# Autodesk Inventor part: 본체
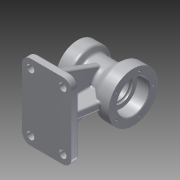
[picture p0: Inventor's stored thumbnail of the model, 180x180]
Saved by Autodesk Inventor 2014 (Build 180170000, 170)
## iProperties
Created: 2015-08
Part Number: 본체
Material: 알루미늄 6061
Document SubType Name: Modeling
Designer: Owner
Density: 2.71 g/cm^3
Appearance: 알루미늄 - 평지
Author: Owner
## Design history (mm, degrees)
sketch "스케치1"
  geometry: C1 r 40 at (0, 0); 1 further point
  constraints: 1 centre point, 1 coincident
  dimensions: "d0" = 80 diameter of C1
extrude "돌출1" new body sketch "스케치1" distance "d1" = 20; taper "d2" = 0 deg
node "작업 평면1"
sketch "스케치2"
  geometry: C1 r 35 at (0, 0); 1 further point
  constraints: 1 centre point, 1 coincident
  dimensions: "d4" = 70 diameter of C1
extrude "돌출2" join sketch "스케치2" distance "d5" = 20; taper "d6" = 0 deg
sketch "스케치3"
  geometry: L1 (0, 40)-(20, 40) reference; L2 (20, 40)-(20, -40) reference; L3 (20, -40)-(0, -40) reference; L4 (0, -40)-(0, 40) reference; L5 (-70, 35)-(-50, 35) reference; L6 (-50, 35)-(-50, -35) reference; L7 (-50, -35)-(-70, -35) reference; L8 (-70, -35)-(-70, 35) reference; L9 (0, 0)-(-50, 0); L10 (0, 40)-(-16.685, 26); L11 (0, 40)-(28.445, 40); L12 (-16.685, 26)-(-44.804, 26); L13 (-50, 35)-(-44.804, 26); L14 (-50, 35)-(-23.111, 35); L15 (-50, 35)-(-50, 0); L16 (0, 40)-(0, 0)
  constraints: 16 end point, 2 horizontal, 1 collinear, 1 midpoint, 1 perpendicular
  dimensions: "d7" = 140 deg angle of L10 L11; "d9" = 60 deg angle of L13 L14
revolve "회전1" sketch "스케치3" stored, may be unused: angle "d10" = 90 deg
node "작업 평면2"
sketch "스케치4"
  geometry: L1 (50, 35)-(50, -35) reference; L2 (70, -35)-(70, 35) reference; L3 (70, 0)-(60, 0); L4 (70, 0)-(70, -61); L5 (70, 0)-(70, 61); L6 (70, -61)-(-10, -61); L7 (70, 61)-(-10, 61); L8 (-10, 61)-(-10, -61); 1 further point
  constraints: 12 end point, 2 equal length, 2 perpendicular, 1 midpoint
  dimensions: "d12" = 10 distance of L3.start L3.end; "d19" = 80 distance of L4.end L6.end
extrude "돌출3" join sketch "스케치4" distance "d17" = 12; taper "d18" = 0 deg
sketch "스케치5"
  geometry: L1 (-44.804, -26)-(-50, -35) reference; L2 (-50, -35)-(-70, -35) reference; L3 (-70, -35)-(-70, 35) reference; L4 (-70, 35)-(-50, 35) reference; L5 (-50, 35)-(-44.804, 26) reference; L6 (-44.804, 26)-(-16.685, 26) reference; L7 (-16.685, 26)-(0, 40) reference; L8 (0, 40)-(20, 40) reference; L9 (20, 40)-(20, -40) reference; L10 (20, -40)-(0, -40) reference; L11 (0, -40)-(-16.685, -26) reference; L12 (-16.685, -26)-(-44.804, -26) reference; L13 (-70, -90)-(-70, -78) reference; L14 (-70, -78)-(10, -78) reference; L15 (10, -78)-(10, -90) reference; L16 (10, -90)-(-70, -90) reference; L17 (-70, -78)-(-60, -78); L18 (-60, -78)-(-60, -30.5); L19 (10, -78)-(0, -78); L20 (0, -78)-(9.169, -26); L21 (9.169, -26)-(-13.066, -13.163); L22 (-13.066, -13.163)-(-38.547, -15.162); L23 (-38.547, -15.162)-(-60, -30.5); 1 further point
  constraints: 14 end point, 2 perpendicular, 2 point on line
  dimensions: "d20" = 10 distance of L13.end L17.end; "d21" = 10 distance of L14.end L19.end; "d22" = 80 deg angle of L19 L20
extrude "돌출4" join sketch "스케치5" stored distance "d23" = 12; taper "d24" = 0 deg
node "작업 평면3"
sketch "스케치6"
  geometry: L1 (0, 0)-(0, 12) reference; L2 (0, 12)-(55, 12) reference; L3 (55, 12)-(55, 64.702) reference; L4 (67, 64.702)-(67, 12) reference; L5 (67, 12)-(122, 12) reference; L6 (122, 12)-(122, 0) reference; L7 (122, 0)-(0, 0) reference; L8 (0, 12)-(10, 12); L9 (10, 12)-(34.734, 79.956); L10 (10, 12)-(82.318, 12); L11 (61, 61.769)-(61, 12); L12 (61, 12)-(10, 12); L13 (61, 61.769)-(61, 90); L14 (61, 90)-(40.606, 82.563); L15 (34.734, 79.956)-(39.044, 91.799); L16 (39.044, 91.799)-(40.606, 82.563); A1 r 26 centre (61, 90) between (67, 64.702) and (55, 64.702) reference; 1 further point
  constraints: 18 end point, 2 collinear, 2 perpendicular, 1 equal length, 1 horizontal, 1 point on line
  dimensions: "d25" = 10 distance of L1.end L8.end; "d26" = 70 deg angle of L10 L9
extrude "돌출5" join sketch "스케치6" stored distance "d27" = 12; taper "d28" = 0 deg
sketch "스케치7"
  geometry: C1 r 40 at (0, 0) reference; C2 r 26 at (0, 0)
  constraints: 1 centre point, 1 coincident
  dimensions: "d29" = 52 diameter of C2
extrude "돌출6" cut sketch "스케치7" distance "d30" = 17; taper "d31" = 0 deg
sketch "스케치8"
  geometry: C1 r 35 at (0, 0) reference; C2 r 20 at (0, 0)
  constraints: 1 centre point, 1 coincident
  dimensions: "d32" = 40 diameter of C2
extrude "돌출7" cut sketch "스케치8" distance "d33" = 20; taper "d34" = 0 deg
sketch "스케치9"
  geometry: C1 r 20 at (0, 0) reference; C2 r 16 at (0, 0)
  constraints: 1 centre point, 1 coincident
  dimensions: "d82" = 32 diameter of C2
node "작업 평면4"
sketch "스케치12" dims "d55" = 54
  geometry: C1 r 35 at (0, 0) reference; C2 r 2 at (0, 27); 1 further point
  constraints: 1 centre point, 1 coincident, 1 vertical alignment, 2 other
  dimensions: "d56" = 4 diameter of C2
hole "구멍2" sketch "스케치12" at (0, 27) diameter "d57" = 3.242; stored, may be unused: countersink angle "d61" = 90 deg, drill point angle "d63" = 118 deg; dims "d58" = 10, "d59" = 4, "d60" = 2, "d62" = 13
sketch "스케치14" dims "d67" = 66
  geometry: C1 r 40 at (0, 0) reference; C2 r 2 at (0, 33); 1 further point
  constraints: 1 centre point, 1 coincident, 1 vertical alignment, 2 other
  dimensions: "d68" = 4 diameter of C2
hole "구멍3" sketch "스케치14" at (0, 33) diameter "d69" = 3.242; stored, may be unused: countersink angle "d73" = 90 deg, drill point angle "d75" = 118 deg; dims "d70" = 10, "d71" = 4, "d72" = 2, "d74" = 13
sketch "스케치15"
  geometry: C1 r 26 at (0, 0) reference; C2 r 26 at (0, 0)
  constraints: 1 centre point, 1 coincident, 1 concentric
extrude "돌출11" cut sketch "스케치9" distance "d83" = 70; taper "d84" = 0 deg
sketch "스케치16"
  geometry: L1 (86.091, 83.185)-(112, 12) reference; L2 (67, 12)-(112, 12) reference; L3 (67, 64.702)-(67, 12) reference; L4 (55, 12)-(55, 64.702) reference; L5 (10, 12)-(55, 12) reference; L6 (10, 12)-(35.909, 83.185) reference; L7 (112, 12)-(122, 12) reference; L8 (122, 12)-(122, 0) reference; L9 (122, 0)-(0, 0) reference; L10 (0, 0)-(0, 12) reference; L11 (0, 12)-(10, 12) reference; L12 (55, 12)-(61, 12); L13 (61, 12)-(61, 30); L14 (37, 42)-(37, 36); L15 (31, 36)-(31, 30); L16 (43, 36)-(43, 30); L17 (85, 30)-(85, 24); L18 (79, 36)-(79, 30); L19 (91, 36)-(91, 30); C1 r 16 at (61, 90) reference; A1 r 26 centre (61, 90) between (35.909, 83.185) and (55, 64.702) reference; A2 r 26 centre (61, 90) between (86.091, 83.185) and (35.909, 83.185) reference; A3 r 26 centre (61, 90) between (67, 64.702) and (86.091, 83.185) reference; A4 r 6 centre (37, 30) between (31, 30) and (43, 30); A5 r 6 centre (37, 36) between (43, 36) and (31, 36); A6 r 6 centre (85, 30) between (79, 30) and (91, 30); A7 r 6 centre (85, 36) between (91, 36) and (79, 36)
  constraints: 16 end point, 11 point on circle, 5 tangent, 4 centre point, 4 parallel, 1 collinear, 1 perpendicular
  dimensions: "d85" = 18 distance of L12.end L13.end; "d87" = 24 distance of L13.end L17.start
extrude "돌출12" cut sketch "스케치16" distance "d91" = 70; taper "d92" = 0 deg
fillet "모깎기1" dims "d93" = 14
sketch "스케치17"
  geometry: A1 r 14 centre (-56, -47) between (-70, -47) and (-56, -61) reference; A2 r 14 centre (-4, -47) between (-4, -61) and (10, -47) reference; A3 r 14 centre (-4, 47) between (10, 47) and (-4, 61) reference; A4 r 14 centre (-56, 47) between (-56, 61) and (-70, 47) reference; 1 further point
hole "구멍4" sketch "스케치17" at (-56, -47), (-4, -47), (-4, 47), (-56, 47) diameter "d94" = 12; stored, may be unused: countersink angle "d98" = 90 deg, drill point angle "d100" = 0 deg; dims "d95" = 10, "d96" = 4, "d97" = 2, "d99" = 30
sketch "스케치18"
  geometry: L1 (-36, -78)-(-60, -78) reference; L2 (-60, -78)-(-44, -78); L3 (-44, -78)-(-44, -54); 2 further points
  constraints: 4 end point, 1 coincident, 1 perpendicular, 1 point on line, 1 other
  dimensions: "d101" = 16 distance of L1.end L2.end; "d102" = 24 distance of L2.end L3.end
feature "엠보싱1" sketch "스케치18" dims "d103" = 0.5, "d104" = 0
fillet "모깎기2" dims "d105" = 5
chamfer "모따기1" distance "d106" = 1; stored, may be unused: second distance "d107" = 2, angle "d108" = 45 deg
fillet "모깎기5" dims "d111" = 3
fillet "모깎기6" dims "d112" = 3
fillet "모깎기7" dims "d113" = 3
fillet "모깎기8" dims "d114" = 3
fillet "모깎기9" dims "d115" = 3
fillet "모깎기10" dims "d116" = 3
fillet "모깎기11" dims "d117" = 3
extrude "돌출13" cut sketch "스케치15" distance "d118" = 3; taper "d119" = 0 deg
sketch "스케치19"
  geometry: C1 r 16 at (0, 0) reference; C2 r 26 at (0, 0) reference; C3 r 19 at (0, 0)
  constraints: 1 centre point, 1 coincident
  dimensions: "d120" = 38 diameter of C3
extrude "돌출14" cut sketch "스케치19" distance "d121" = 3; taper "d122" = 0 deg
fillet "모깎기12" dims "d123" = 3
sketch "스케치20"
  geometry: C1 r 16 at (0, 0) reference; C2 r 20 at (0, 0) reference; C3 r 20 at (0, 0)
  constraints: 1 centre point, 1 coincident, 1 concentric
extrude "돌출15" cut sketch "스케치20" distance "d125" = 3; taper "d126" = 0 deg
sketch "스케치22"
  geometry: C1 r 16 at (0, 0) reference; C2 r 20 at (0, 0) reference; C3 r 20 at (0, 0)
  constraints: 1 centre point, 1 coincident, 1 concentric
extrude "돌출16" join sketch "스케치22" distance "d128" = 6; taper "d129" = 0 deg
fillet "모깎기15" dims "d130" = 0.3
node "솔리드1"
mirror "대칭1"
pattern_circular "원형 패턴2" dims angle "d65" = 360 deg
pattern_circular "원형 패턴3" dims angle "d77" = 360 deg
node "투영된 루프1"
node "절단 모서리 투영1"
node "절단 모서리 투영2"
node "절단 모서리 투영3"
node "절단 모서리 투영4"
